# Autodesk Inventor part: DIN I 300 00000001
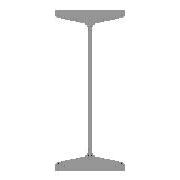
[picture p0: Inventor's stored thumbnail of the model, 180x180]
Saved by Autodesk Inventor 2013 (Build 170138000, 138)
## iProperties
IsCustomPart: 1
Created: 2009-11
Part Number: DIN I 300 00000001
Material: Steel, Mild
Description: Hot rolled I-beam
Document SubType Name: Modeling
Standard: DIN
Designer: pokornp
Standard Revision: 1995
Standards Organization: DIN
Language: en-US
Size Designation: I 300
Categories: <MemberInstance><Categories><Category DisplayName="Structural Shapes" InternalName="089c4875-fa83-4c05-b084-43b9cc11f5ed" Mnemonic="GRDR"><CategoryParameter Dis
Stock Number: I 300
Density: 7.86 g/cm^3
Sheet Metal Rule: Default
_CCFamilyMember: 120
_CCFamilyDisplayName: DIN 1025-1 - Hot rolled I-beam
_FrameMemberDoc: Frame Member File
_Version: 15.0.0
G_L: 10000.000 mm
G_W: 125.000 mm
G_H: 300.000 mm
Author: pokornp
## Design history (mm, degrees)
node "Start plane"
node "End plane"
sketch "Sketch"
  geometry: L1 (5.4, -120.788)-(5.4, 120.788); L2 (-62.5, -150)-(62.5, -150); L3 (-5.4, 120.788)-(-5.4, -120.788); L4 (62.5, 150)-(-62.5, 150); L5 (0, -210)-(0, 210) reference; L6 (-89.185, 0)-(89.185, 0) reference; L7 (-62.5, 150)-(-62.5, 143.828); L8 (-56.901, 137.391)-(-14.703, 131.483); L9 (62.5, 150)-(62.5, 143.828); L10 (56.901, 137.391)-(14.703, 131.483); L11 (-56.901, -137.391)-(-14.703, -131.483); L12 (14.703, -131.483)-(56.901, -137.391); L13 (62.5, -143.828)-(62.5, -150); L14 (-62.5, -150)-(-62.5, -143.828); A1 r 6.5 centre (-56, 143.828) between (-62.5, 143.828) and (-56.901, 137.391); A2 r 6.5 centre (56, 143.828) between (56.901, 137.391) and (62.5, 143.828); A3 r 6.5 centre (56, -143.828) between (62.5, -143.828) and (56.901, -137.391); A4 r 6.5 centre (-56, -143.828) between (-56.901, -137.391) and (-62.5, -143.828); A5 r 10.8 centre (-16.2, 120.788) between (-5.4, 120.788) and (-14.703, 131.483); A6 r 10.8 centre (16.2, 120.788) between (14.703, 131.483) and (5.4, 120.788); A7 r 10.8 centre (16.2, -120.788) between (5.4, -120.788) and (14.703, -131.483); A8 r 10.8 centre (-16.2, -120.788) between (-14.703, -131.483) and (-5.4, -120.788); 6 further points
  constraints: 24 end point, 16 point on circle, 16 tangent, 9 point on line, 8 centre point, 6 equal radius, 4 equal length, 3 parallel, 2 horizontal, 2 vertical, 1 perpendicular, 1 symmetric about line, 3 other
  dimensions: "d3" = 300 vertical distance of L2.end L4.end (= ParH); "d17" = 125 distance of L4.start L4.end (= b); "d22" = 10.8 distance between parallel lines of L3 L1 (= t1); "d28" = 150 distance between parallel lines of L2 L6 (= 0.5 x d3); "d31" = 7.96961 deg angle of L4 L8; "d32" = 31.25 distance from line of point (31.25, -133.8) L13 (= 0.25 x b); "d33" = 16.2 distance from line of L2 point (31.25, -133.8) (= t2); "d34" = 6.5 radius of A1 (= R1); "d35" = 10.8 radius of A5 (= R)
extrude "Body" new body sketch "Sketch" stored distance "d18" = 10000 (= G_L); taper "d19" = 0 deg
node "Driven Length"
  sketch "Sketch3"
    geometry: L1 (0, 0)-(10, 0) reference
    constraints: 2 end point, 1 horizontal
  workplane "Work Plane7"
  sketch "Sketch4"
    geometry: L1 (-2, 0)-(12, 0) reference; L2 (-2, 10000)-(12, 10000) reference
    dimensions: "d37" = 10000 distance between parallel lines of L1 L2 (derived)
body "Solid1"
other parameters: "b" = 125 [user parameter; used in 4 equation terms], "ParH" = 300 [user parameter; used in 1 equation term], "R1" = 6.5 [user parameter; used in 1 equation term], "t1" = 10.8 [user parameter; used in 2 equation terms], "t2" = 16.2 [user parameter; used in 1 equation term], "msp_pom" = 51.7 (= 0.5 x b - t1) [user parameter; used in 1 equation term], "msp_x1" = 3.619 (= 0.07 x msp_pom) [user parameter], "msp_x2" = 4.375 (= 0.035 x b) [user parameter], "G_L" = 10000 (= d37) [user parameter; used in 1 equation term], "R" = 10.8 [user parameter; used in 1 equation term], "d4" = 4.25 (derived), "d6" = 7.47 (derived), "d8" = 0 (derived), "d10" = 0 (derived), "d12" = 4.25 (derived), "d14" = 4.25 (derived), "G_OFFSET_START" = 0 [user parameter; used in 1 equation term], "G_OFFSET_END" = 0 [user parameter; used in 1 equation term], "d29" = 0 (computed from G_OFFSET_START), "Thickness" = 0.5, "BendRadius" = 0.5 (= Thickness), "BendReliefWidth" = 0.5 (= Thickness), "BendReliefDepth" = 0.25 (= 0.5 x Thickness), "CornerReliefSize" = 2 (= 4 x Thickness), "SeamGap" = 0.01, "MinimumRemnant" = 1 (= 2 x Thickness), "TransitionRadius" = 0.5 (= BendRadius), "JacobiRadiusSize" = 0.5 (= Thickness), "d36" = 90 deg, "GapSize" = 0.5 (= Thickness)
